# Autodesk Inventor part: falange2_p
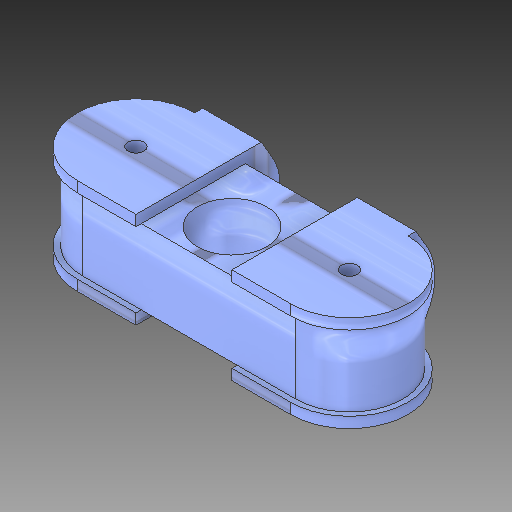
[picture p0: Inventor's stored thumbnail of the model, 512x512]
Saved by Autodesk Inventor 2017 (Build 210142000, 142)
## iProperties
Created: 2017-05
Part Number: falange2_p
Material: Generic
Document SubType Name: Modeling
Designer: alez_
Density: 1 g/cm^3
Appearance: Default
Author: alez_
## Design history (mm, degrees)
derived "Falange_2.ipt" dims "d0" = 9
feature "Solid1::Falange_2.ipt" dims "d0" = 9
tag "TaggingFeature1"
body "Solid1"
